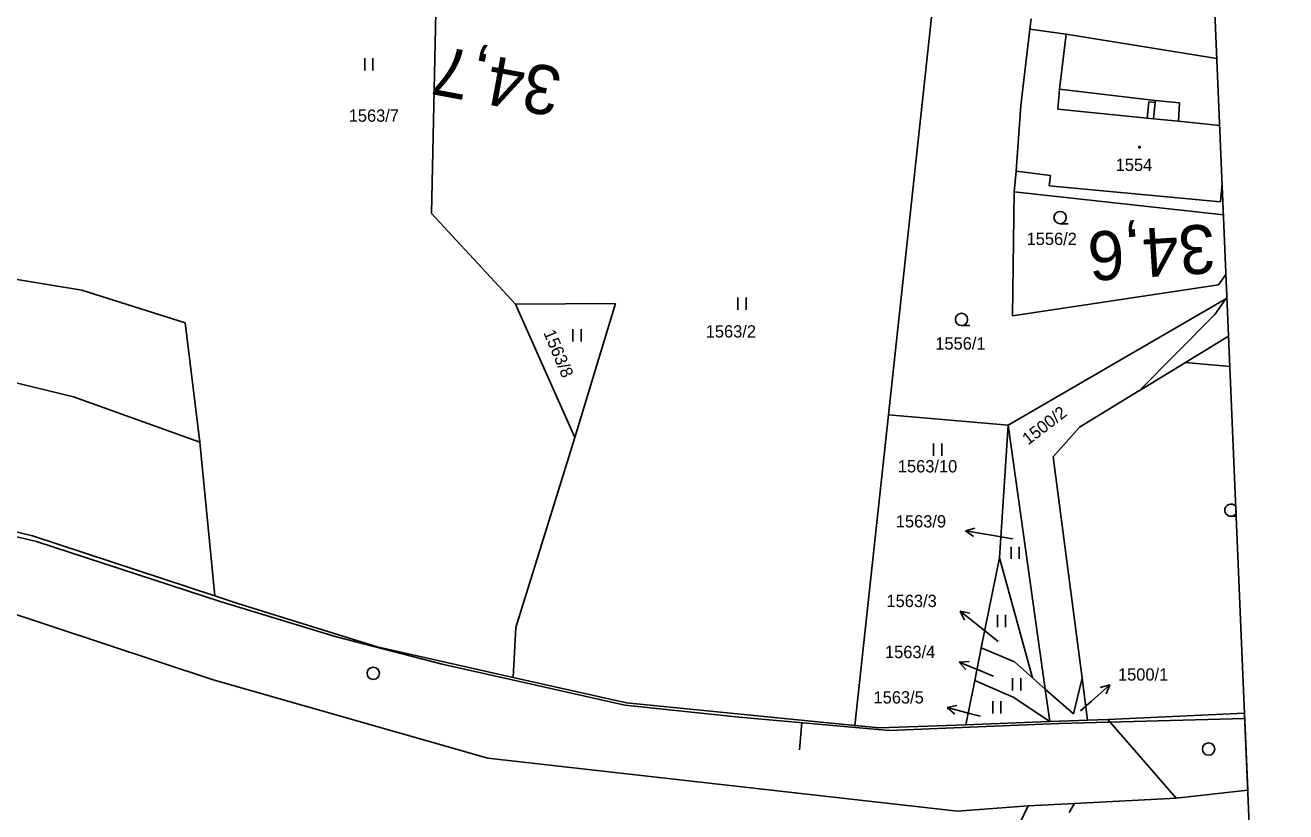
# Model space of a CAD drawing. Extents: x -806456 to -805395, y -1150847 to -1150506.
# Drawn here: x -805548.5 to -805394.6, y -1150696.2 to -1150600.2 of the extents above; entities that cross this region are included whole.
import ezdxf

# ---------------------------------------------------------------- set-up
doc = ezdxf.new("R2010")
doc.units = 0
for name, color, linetype in [('Default', 7, 'Continuous'), ('formát', 7, 'Continuous'), ('kilometráž - vrstava 7', 7, 'Continuous'), ('kn_celek - Cisla parcel pomocna', 7, 'Continuous'), ('kn_celek - Cisla pozemkovych parcel', 7, 'Continuous'), ('kn_celek - Cisla stavebnich parcel', 7, 'Continuous'), ('kn_celek - Hranice parcel', 7, 'Continuous'), ('kn_celek - Vnitrni kresby', 7, 'Continuous'), ('kn_celek - Znacky budov', 7, 'Continuous'), ('kn_celek - Znacky kultur', 7, 'Continuous'), ('plochy - SZDC', 7, 'Continuous'), ('PSR_C2_2_trasa_Vimperk - Kabelová trasa', 7, 'Continuous')]:
    doc.layers.add(name, color=color, linetype=linetype)

# ---------------------------------------------------------------- blocks, each defined once
blk = doc.blocks.new('304')
at = {"layer": 'Default'}
blk.add_line((-0.1, 0), (9.9, 0), dxfattribs=at)
blk.add_circle((-0.1, 7.5), 7.5, dxfattribs=at)
blk = doc.blocks.new('306')
at = {"layer": 'Default'}
for p, q in [((-5.2, 0), (-5.2, 15)), ((4.8, 0), (4.8, 15))]:
    blk.add_line(p, q, dxfattribs=at)
blk = doc.blocks.new('402')
at = {"layer": 'Default'}
for p, q in [((-0.8, 0.8), (0.7, 0.8)), ((-0.8, 0.8), (-0.8, -0.7)), ((0.7, 0.8), (0.7, -0.7)), ((0.7, -0.7), (-0.8, -0.7))]:
    blk.add_line(p, q, dxfattribs=at)
blk = doc.blocks.new('Z61')
at = {"layer": 'Default'}
for p, q in [((0, 0), (30, 0)), ((30, 0), (19.2, 5.3)), ((30, 0), (19.2, -5.3))]:
    blk.add_line(p, q, dxfattribs=at)

msp = doc.modelspace()

# ---------------------------------------------------------------- linework, layer by layer
at = {"layer": 'Default'}
for p, q in [((-805401.32, -1150660.14), (-805400.66, -1150660.14)), ((-805400.68, -1150659.78), (-805400.72, -1150658.94))]:
    msp.add_line(p, q, dxfattribs=at)
msp.add_arc((-805401.32, -1150659.39), 0.75, 36.6268, 328.2347, dxfattribs=at)
at = {"layer": 'formát'}
msp.add_line((-805407.21, -1150506.06), (-805394.61, -1150802.8), dxfattribs=at)
at = {"layer": 'kilometráž - vrstava 7'}
for centre in [(-805506.04, -1150679.31), (-805404.03, -1150688.55)]:
    msp.add_circle(centre, 0.75, dxfattribs=at)
at = {"layer": 'kn_celek - Cisla parcel pomocna'}
for p, q in [((-805428, -1150662.88), (-805430.77, -1150662.41)), ((-805429.72, -1150675.42), (-805432.02, -1150673.59)), ((-805430.36, -1150679.64), (-805431.7, -1150679.09)), ((-805419.69, -1150683.87), (-805418.35, -1150682.69)), ((-805431.94, -1150684.55), (-805433.05, -1150684.26))]:
    msp.add_line(p, q, dxfattribs=at)
at = {"layer": 'kn_celek - Hranice parcel'}
for p, q in [((-805498.17, -1150587.83), (-805498.93, -1150623.15)), ((-805437.68, -1150597.31), (-805443.12, -1150647.75)), ((-805425.86, -1150600.64), (-805425.71, -1150599.38)), ((-805426.96, -1150609.96), (-805425.86, -1150600.64)), ((-805425.86, -1150600.64), (-805421.43, -1150601.26)), ((-805421.43, -1150601.26), (-805403.04, -1150604.22)), ((-805427.52, -1150617.99), (-805426.96, -1150609.96)), ((-805427.76, -1150620.52), (-805427.52, -1150617.99)), ((-805427.76, -1150620.52), (-805427.97, -1150635.67)), ((-805402.23, -1150623.31), (-805427.76, -1150620.52)), ((-805498.93, -1150623.15), (-805488.68, -1150634.22)), ((-805541.61, -1150632.52), (-805562.96, -1150629.07)), ((-805402.84, -1150631.87), (-805401.92, -1150630.63)), ((-805541.61, -1150632.52), (-805529, -1150636.53)), ((-805427.97, -1150635.67), (-805402.84, -1150631.87)), ((-805401.93, -1150633.6), (-805428.5, -1150648.99)), ((-805403.27, -1150635.51), (-805401.93, -1150633.6)), ((-805401.79, -1150633.52), (-805401.93, -1150633.6)), ((-805488.68, -1150634.22), (-805476.47, -1150634.17)), ((-805488.68, -1150634.22), (-805481.42, -1150650.51)), ((-805476.47, -1150634.17), (-805481.42, -1150650.51)), ((-805412.53, -1150644.8), (-805403.27, -1150635.51)), ((-805529, -1150636.53), (-805527.22, -1150651.09)), ((-805406.84, -1150641.34), (-805401.6, -1150638.15)), ((-805542.66, -1150645.56), (-805568.04, -1150639.35)), ((-805406.84, -1150641.34), (-805412.53, -1150644.8)), ((-805401.44, -1150641.83), (-805406.84, -1150641.34)), ((-805412.56, -1150644.82), (-805419.82, -1150649.25)), ((-805412.53, -1150644.8), (-805412.56, -1150644.82)), ((-805527.22, -1150651.09), (-805542.66, -1150645.56)), ((-805443.12, -1150647.75), (-805447.24, -1150685.68)), ((-805443.12, -1150647.75), (-805428.5, -1150648.99)), ((-805429.56, -1150665.22), (-805428.5, -1150648.99)), ((-805428.5, -1150648.99), (-805423.98, -1150681.23)), ((-805423.01, -1150652.86), (-805419.82, -1150649.25)), ((-805481.42, -1150650.51), (-805488.65, -1150673.73)), ((-805527.22, -1150651.09), (-805525.39, -1150669.85)), ((-805423.01, -1150652.86), (-805419.48, -1150679.92)), ((-805573.24, -1150656.2), (-805547.66, -1150662.54)), ((-805547.66, -1150662.54), (-805525.39, -1150669.85)), ((-805429.56, -1150665.22), (-805431.79, -1150676.21)), ((-805429.56, -1150665.22), (-805425.54, -1150679.86)), ((-805525.6, -1150680.1), (-805553.22, -1150670.95)), ((-805525.39, -1150669.85), (-805522.57, -1150670.78)), ((-805522.57, -1150670.78), (-805505.56, -1150676.07)), ((-805488.65, -1150673.73), (-805488.96, -1150679.81)), ((-805488.96, -1150679.81), (-805505.56, -1150676.07)), ((-805431.79, -1150676.21), (-805432.6, -1150680.19)), ((-805427.75, -1150677.92), (-805431.79, -1150676.21)), ((-805425.54, -1150679.86), (-805427.75, -1150677.92)), ((-805492.06, -1150689.65), (-805525.6, -1150680.1)), ((-805475.13, -1150682.93), (-805488.96, -1150679.81)), ((-805432.6, -1150680.19), (-805433.7, -1150685.59)), ((-805432.6, -1150680.19), (-805427.91, -1150682.2)), ((-805423.98, -1150681.23), (-805425.54, -1150679.86)), ((-805420.52, -1150684.26), (-805419.48, -1150679.92)), ((-805419.48, -1150679.92), (-805418.81, -1150685.03)), ((-805423.42, -1150685.2), (-805423.98, -1150681.23)), ((-805420.52, -1150684.26), (-805423.98, -1150681.23)), ((-805475.13, -1150682.93), (-805447.24, -1150685.68)), ((-805427.91, -1150682.2), (-805423.42, -1150685.2)), ((-805399.64, -1150684.18), (-805416.34, -1150684.94)), ((-805447.24, -1150685.68), (-805444.22, -1150685.98)), ((-805433.7, -1150685.59), (-805444.22, -1150685.98)), ((-805423.42, -1150685.2), (-805433.7, -1150685.59)), ((-805423.42, -1150685.2), (-805419.87, -1150685.07)), ((-805419.87, -1150685.07), (-805418.81, -1150685.03)), ((-805418.81, -1150685.03), (-805416.34, -1150684.94)), ((-805416.34, -1150684.94), (-805408.01, -1150694.56)), ((-805434.71, -1150696.14), (-805492.06, -1150689.65)), ((-805408.01, -1150694.56), (-805399.25, -1150693.56)), ((-805426.08, -1150695.49), (-805434.71, -1150696.14)), ((-805429.45, -1150702.56), (-805426.08, -1150695.49)), ((-805420.42, -1150695.2), (-805426.08, -1150695.49)), ((-805421.06, -1150696.29), (-805420.42, -1150695.2)), ((-805420.42, -1150695.2), (-805408.01, -1150694.56))]:
    msp.add_line(p, q, dxfattribs=at)
at = {"layer": 'kn_celek - Vnitrni kresby'}
for p, q in [((-805421.43, -1150601.26), (-805422.26, -1150608)), ((-805422.26, -1150608), (-805422.43, -1150610.42)), ((-805422.26, -1150608), (-805410.54, -1150609.36)), ((-805410.54, -1150609.36), (-805410.55, -1150609.61)), ((-805410.54, -1150609.36), (-805407.6, -1150609.64)), ((-805422.43, -1150610.42), (-805411.55, -1150611.52)), ((-805411.55, -1150611.52), (-805411.34, -1150609.53)), ((-805411.34, -1150609.53), (-805410.55, -1150609.61)), ((-805410.55, -1150609.61), (-805410.75, -1150611.6)), ((-805407.6, -1150609.64), (-805407.73, -1150611.91)), ((-805410.75, -1150611.6), (-805411.55, -1150611.52)), ((-805410.75, -1150611.6), (-805407.73, -1150611.91)), ((-805407.73, -1150611.91), (-805402.69, -1150612.42)), ((-805423.33, -1150618.54), (-805427.52, -1150617.99)), ((-805423.49, -1150619.78), (-805423.33, -1150618.54)), ((-805402.59, -1150621.76), (-805423.49, -1150619.78)), ((-805402.39, -1150619.52), (-805402.59, -1150621.76))]:
    msp.add_line(p, q, dxfattribs=at)
at = {"layer": 'plochy - SZDC'}
for p, q in [((-805547.66, -1150662.54), (-805573.24, -1150656.2)), ((-805525.39, -1150669.85), (-805547.66, -1150662.54)), ((-805553.22, -1150670.95), (-805525.6, -1150680.1)), ((-805522.57, -1150670.78), (-805525.39, -1150669.85)), ((-805505.56, -1150676.07), (-805522.57, -1150670.78)), ((-805488.96, -1150679.81), (-805505.56, -1150676.07)), ((-805525.6, -1150680.1), (-805492.06, -1150689.65)), ((-805475.13, -1150682.93), (-805488.96, -1150679.81)), ((-805447.24, -1150685.68), (-805475.13, -1150682.93)), ((-805399.64, -1150684.18), (-805416.34, -1150684.94)), ((-805399.25, -1150693.56), (-805399.64, -1150684.18)), ((-805444.22, -1150685.98), (-805447.24, -1150685.68)), ((-805433.7, -1150685.59), (-805444.22, -1150685.98)), ((-805423.42, -1150685.2), (-805433.7, -1150685.59)), ((-805419.87, -1150685.07), (-805423.42, -1150685.2)), ((-805418.81, -1150685.03), (-805419.87, -1150685.07)), ((-805416.34, -1150684.94), (-805418.81, -1150685.03)), ((-805408.01, -1150694.56), (-805416.34, -1150684.94)), ((-805416.34, -1150684.94), (-805408.01, -1150694.56)), ((-805492.06, -1150689.65), (-805434.71, -1150696.14)), ((-805408.01, -1150694.56), (-805399.25, -1150693.56)), ((-805434.71, -1150696.14), (-805426.08, -1150695.49)), ((-805426.08, -1150695.49), (-805420.42, -1150695.2)), ((-805420.42, -1150695.2), (-805408.01, -1150694.56))]:
    msp.add_line(p, q, dxfattribs=at)
at = {"layer": 'PSR_C2_2_trasa_Vimperk - Kabelová trasa'}
msp.add_line((-805453.99, -1150688.64), (-805453.72, -1150685.33), dxfattribs=at)
for points in [[(-805624.23, -1150651.13), (-805607.21, -1150652.21), (-805573.59, -1150656.97), (-805547.17, -1150663.21), (-805524.75, -1150670.52), (-805510.68, -1150674.8), (-805497.62, -1150678.19), (-805486.72, -1150680.63), (-805475.31, -1150683.18), (-805461.35, -1150684.65), (-805443.05, -1150686.29), (-805422.27, -1150685.42)], [(-805422.27, -1150685.42), (-805399.62, -1150684.81)]]:
    msp.add_lwpolyline(points, dxfattribs=at)

# ---------------------------------------------------------------- block references
at = {"layer": 'kn_celek - Cisla parcel pomocna'}
for p, xscale, yscale, rotation in [((-805430.77, -1150662.41), 0.1, 0.10000000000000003, 170.4366), ((-805432.02, -1150673.59), 0.09999999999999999, 0.10000000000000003, 141.49071000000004), ((-805431.7, -1150679.09), 0.09999999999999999, 0.10000000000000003, 157.69692), ((-805418.35, -1150682.69), 0.1, 0.10000000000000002, 41.444730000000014), ((-805433.05, -1150684.26), 0.09999999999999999, 0.10000000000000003, 165.19320000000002)]:
    msp.add_blockref('Z61', p, dxfattribs=dict(at, xscale=xscale, yscale=yscale, rotation=rotation))
at = {"layer": 'kn_celek - Znacky budov', "xscale": 0.1, "yscale": 0.10000000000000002}
msp.add_blockref('402', (-805412.48, -1150615.07), dxfattribs=at)
at = {"layer": 'kn_celek - Znacky kultur', "xscale": 0.1, "yscale": 0.10000000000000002}
for name, p in [('306', (-805506.57, -1150605.71)), ('304', (-805422.16, -1150624.41)), ('306', (-805460.99, -1150634.94)), ('304', (-805434.2, -1150636.84)), ('306', (-805481.14, -1150638.78)), ('306', (-805437.1, -1150652.75)), ('306', (-805427.64, -1150665.35)), ('306', (-805429.31, -1150673.67)), ('306', (-805427.46, -1150681.41)), ('306', (-805429.88, -1150684.22))]:
    msp.add_blockref(name, p, dxfattribs=at)

# ---------------------------------------------------------------- texts
at = {"layer": 'kilometráž - vrstava 7'}
for s, height, rotation, p in [('34,7', 6, 169.5145, (-805482.74, -1150605.49)), ('34,6', 5.969, 183.7495, (-805403.44, -1150624.44))]:
    msp.add_text(s, height=height, rotation=rotation, dxfattribs=at).set_placement(p)
at = {"layer": 'kn_celek - Cisla parcel pomocna'}
for s, p in [('1563/9', (-805442.23, -1150661.5)), ('1563/3', (-805443.37, -1150671.22)), ('1563/4', (-805443.55, -1150677.45)), ('1500/1', (-805415.1, -1150680.2)), ('1563/5', (-805444.95, -1150682.99))]:
    msp.add_text(s, height=1.5, dxfattribs=at).set_placement(p)
at = {"layer": 'kn_celek - Cisla pozemkovych parcel'}
for s, height, p in [('1563/7', 1.5, (-805509.04, -1150611.96)), ('1556/2', 1.5, (-805426.26, -1150627.01)), ('1563/2', 1.5, (-805465.44, -1150638.31)), ('1556/1', 1.5, (-805437.41, -1150639.78)), ('1563/10', 1.5, (-805441.98, -1150654.78)), ('1563/9', 0.1, (-805428.26, -1150662.85)), ('1563/3', 0.1, (-805429.99, -1150675.39)), ('1563/4', 0.1, (-805430.63, -1150679.61)), ('1563/5', 0.1, (-805432.21, -1150684.52)), ('1500/1', 0.1, (-805419.94, -1150683.84))]:
    msp.add_text(s, height=height, dxfattribs=at).set_placement(p)
for s, rotation, p in [('1563/8', 292.697, (-805485.29, -1150637.71)), ('1500/2', 37.5789, (-805426.07, -1150651.5))]:
    msp.add_text(s, height=1.5, rotation=rotation, dxfattribs=at).set_placement(p)
at = {"layer": 'kn_celek - Cisla stavebnich parcel'}
msp.add_text('1554', height=1.5, dxfattribs=at).set_placement((-805415.38, -1150617.97))

doc.saveas('drawing.dxf')
